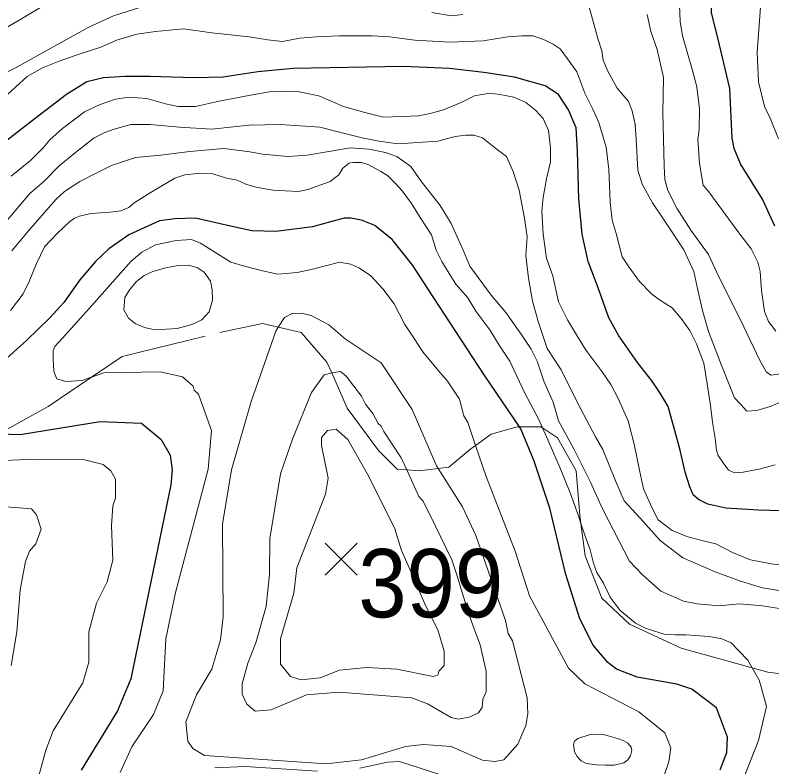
# Model space of a CAD drawing. Extents: x 474.5 to 500, y 7345.7 to 7373.4.
# Drawn here: x 484.682 to 485.568, y 7367.259 to 7368.139 of the extents above; entities that cross this region are included whole.
import ezdxf
from ezdxf.enums import TextEntityAlignment as Align

# ---------------------------------------------------------------- set-up
doc = ezdxf.new("R2010")
doc.units = 0
doc.header["$LTSCALE"] = 0.032
doc.linetypes.add('SHORT_DASHED', pattern=[2.7, 1.5, -1.2])
for name, color, linetype, lineweight in [('1', 7, 'Continuous', 25), ('16', 7, 'SHORT_DASHED', 13), ('2', 7, 'Continuous', 13), ('21', 7, 'Continuous', 25)]:
    doc.layers.add(name, color=color, linetype=linetype, lineweight=lineweight)
doc.layers.add('61', color=7, linetype='Continuous')

msp = doc.modelspace()

# ---------------------------------------------------------------- linework, layer by layer
at = {"layer": '1'}
for points in [[(485.5714, 7367.8924), (485.5571, 7367.9237), (485.5312, 7367.9653), (485.5237, 7367.983), (485.5216, 7367.9953), (485.5189, 7368.0532), (485.5134, 7368.0764), (485.5066, 7368.1044), (485.4971, 7368.1425), (485.4964, 7368.1752), (485.5039, 7368.2073), (485.508, 7368.2216), (485.5134, 7368.2359), (485.5243, 7368.2509), (485.5448, 7368.2727), (485.5666, 7368.2952), (485.5789, 7368.3109)], [(485.6463, 7367.5573), (485.5524, 7367.5597), (485.514, 7367.562), (485.4929, 7367.5667), (485.4819, 7367.5722), (485.4757, 7367.5777), (485.4718, 7367.5871), (485.4663, 7367.6043), (485.4608, 7367.6301), (485.4538, 7367.6544), (485.4467, 7367.681), (485.4373, 7367.6966), (485.4279, 7367.7107), (485.4107, 7367.7326), (485.3888, 7367.7639), (485.3771, 7367.785), (485.3646, 7367.8202), (485.3528, 7367.8508), (485.3458, 7367.8828), (485.3419, 7367.9243), (485.3403, 7367.9799), (485.3387, 7368.0073), (485.3301, 7368.0284), (485.3184, 7368.0464), (485.3027, 7368.0566), (485.2668, 7368.0667), (485.2308, 7368.0722), (485.1908, 7368.0769), (485.1369, 7368.0792), (485.05, 7368.0777), (485.0077, 7368.0769), (484.9663, 7368.073), (484.9256, 7368.0667), (484.8919, 7368.0659), (484.8403, 7368.0675), (484.8106, 7368.0675), (484.7855, 7368.0659), (484.766, 7368.0613), (484.7425, 7368.0464), (484.7057, 7368.0182), (484.6674, 7367.9885)], [(485.5073, 7367.2558), (485.5153, 7367.2764), (485.516, 7367.2941), (485.5033, 7367.3284), (485.4741, 7367.3502), (485.4567, 7367.3562), (485.4104, 7367.3644), (485.386, 7367.3736), (485.3759, 7367.3817), (485.3589, 7367.402), (485.3433, 7367.4325), (485.3268, 7367.4847), (485.3082, 7367.562), (485.2898, 7367.6173), (485.2741, 7367.655), (485.2724, 7367.6575), (485.2313, 7367.7183), (485.165, 7367.8195), (485.1478, 7367.8461), (485.1236, 7367.8766), (485.1032, 7367.893), (485.0876, 7367.8993), (485.075, 7367.9016), (485.0672, 7367.9016), (485.0531, 7367.8977), (485.0304, 7367.8915), (484.9874, 7367.886), (484.9592, 7367.8868), (484.9342, 7367.8922), (484.8935, 7367.9016), (484.8692, 7367.9008), (484.8512, 7367.8985), (484.8153, 7367.8821), (484.7918, 7367.8656), (484.7761, 7367.8508), (484.7581, 7367.8296), (484.7394, 7367.803), (484.7229, 7367.785), (484.6955, 7367.7584), (484.665, 7367.731)], [(484.6628, 7367.6491), (484.6883, 7367.6484), (484.7818, 7367.6635), (484.8303, 7367.6618), (484.8531, 7367.6427), (484.8635, 7367.6244), (484.8659, 7367.6071), (484.8643, 7367.5893), (484.8176, 7367.3624), (484.8022, 7367.3248), (484.7597, 7367.2556)]]:
    msp.add_lwpolyline(points, dxfattribs=at)
at = {"layer": '16'}
msp.add_lwpolyline([(484.6628, 7367.6491), (484.721, 7367.6813), (484.7716, 7367.7155), (484.8074, 7367.7396), (484.9219, 7367.7677), (484.9716, 7367.7785), (484.9902, 7367.7741), (485.017, 7367.7677), (485.0472, 7367.7331), (485.0528, 7367.7204), (485.071, 7367.6791), (485.1077, 7367.6295), (485.1293, 7367.6079), (485.1405, 7367.607), (485.1552, 7367.6057), (485.1774, 7367.6085), (485.1897, 7367.61), (485.2157, 7367.6316), (485.2212, 7367.6356), (485.2394, 7367.6489), (485.2697, 7367.6575), (485.2724, 7367.6575), (485.2977, 7367.6575), (485.2996, 7367.6562), (485.3172, 7367.6446), (485.3388, 7367.6057), (485.3431, 7367.5539), (485.3444, 7367.5443), (485.3496, 7367.5063), (485.369, 7367.4567), (485.4014, 7367.4264), (485.4619, 7367.3983), (485.5449, 7367.3754), (485.5634, 7367.3703), (485.6649, 7367.3573)], dxfattribs=at)
at = {"layer": '2'}
for points in [[(485.5758, 7367.9946), (485.5658, 7368.0187), (485.5594, 7368.0324), (485.5524, 7368.0612), (485.5509, 7368.0958), (485.5545, 7368.1484), (485.5579, 7368.1885), (485.5636, 7368.22), (485.5795, 7368.2577)], [(485.5725, 7367.7695), (485.564, 7367.7806), (485.5592, 7367.7922), (485.5558, 7367.8171), (485.5541, 7367.839), (485.5515, 7367.8501), (485.5438, 7367.8656), (485.5292, 7367.8844), (485.4941, 7367.9325), (485.4876, 7367.9402), (485.4833, 7367.9655), (485.4812, 7367.9942), (485.4829, 7368.0054), (485.4833, 7368.0294), (485.4803, 7368.0555), (485.4752, 7368.0744), (485.4632, 7368.1152), (485.4606, 7368.1319), (485.4593, 7368.1606)], [(484.7245, 7368.1556), (484.687, 7368.1332)], [(484.8292, 7368.1486), (484.7972, 7368.1384), (484.7679, 7368.1248), (484.7249, 7368.1009), (484.6833, 7368.0778), (484.6554, 7368.0641)], [(485.2061, 7368.1398), (485.1931, 7368.1384), (485.17, 7368.1425)], [(485.4092, 7367.9939), (485.4078, 7368.011), (485.4085, 7368.0096), (485.4044, 7368.0273), (485.4003, 7368.0382), (485.3867, 7368.0539), (485.3758, 7368.0737), (485.3703, 7368.0866), (485.369, 7368.0975), (485.3642, 7368.1118), (485.3587, 7368.1316), (485.354, 7368.1486)], [(484.687, 7368.1332), (484.6372, 7368.1044)], [(485.5782, 7367.7193), (485.5673, 7367.7179), (485.5618, 7367.7213), (485.5537, 7367.735), (485.5312, 7367.7827), (485.5059, 7367.8331), (485.4937, 7367.859), (485.4732, 7367.8876), (485.4569, 7367.9135), (485.446, 7367.934), (485.4426, 7367.9469), (485.4419, 7367.9626), (485.4405, 7368.0253), (485.4412, 7368.0662), (485.4337, 7368.0989), (485.4262, 7368.12), (485.4221, 7368.1398)], [(485.23, 7368.109), (485.1916, 7368.1074), (485.1502, 7368.1098), (485.1204, 7368.1137), (485.1001, 7368.1152), (485.061, 7368.1152), (485.0351, 7368.1137), (485.0156, 7368.1121), (484.9952, 7368.1082), (484.978, 7368.1105), (484.9561, 7368.1137), (484.9342, 7368.116), (484.9123, 7368.1184), (484.8794, 7368.1231), (484.8466, 7368.1199), (484.8246, 7368.1168), (484.802, 7368.1105), (484.7824, 7368.1019), (484.755, 7368.0926), (484.7339, 7368.0855), (484.7143, 7368.0777), (484.6963, 7368.0675), (484.6689, 7368.0425)], [(485.5719, 7367.6129), (485.5547, 7367.6082), (485.5344, 7367.6043), (485.5242, 7367.6035), (485.5171, 7367.6066), (485.5109, 7367.6152), (485.505, 7367.624), (485.5031, 7367.6301), (485.5015, 7367.6442), (485.4984, 7367.663), (485.496, 7367.6825), (485.4921, 7367.7076), (485.4882, 7367.7318), (485.4796, 7367.7545), (485.4718, 7367.7702), (485.4616, 7367.7842), (485.4514, 7367.7968), (485.4366, 7367.8062), (485.4272, 7367.8132), (485.4131, 7367.8273), (485.4006, 7367.8445), (485.3927, 7367.8562), (485.3857, 7367.8836), (485.381, 7367.8993), (485.3786, 7367.9204), (485.3771, 7367.9587), (485.374, 7367.9846), (485.3653, 7368.0135), (485.3583, 7368.0292), (485.3489, 7368.0479), (485.3395, 7368.073), (485.3286, 7368.0879), (485.32, 7368.0996), (485.3121, 7368.1051), (485.3027, 7368.1098), (485.2887, 7368.1152), (485.2754, 7368.1152), (485.2589, 7368.1137), (485.23, 7368.109)], [(485.1345, 7368.0206), (485.1134, 7368.0198), (485.0915, 7368.0253), (485.0664, 7368.0323), (485.0523, 7368.0386), (485.0375, 7368.0448), (485.0148, 7368.0495), (484.9843, 7368.0503), (484.9577, 7368.0456), (484.9209, 7368.0386), (484.8935, 7368.0323), (484.8732, 7368.0323), (484.8583, 7368.0354), (484.8364, 7368.0417), (484.8153, 7368.0433), (484.7996, 7368.0409), (484.7816, 7368.0346), (484.7636, 7368.026), (484.7378, 7368.0065), (484.7229, 7367.9932), (484.7151, 7367.9838), (484.7002, 7367.9689), (484.6775, 7367.9509)], [(485.611, 7367.4924), (485.5672, 7367.4971), (485.543, 7367.5018), (485.5218, 7367.5104), (485.5023, 7367.5206), (485.4858, 7367.5245), (485.4686, 7367.5292), (485.4514, 7367.5362), (485.435, 7367.5487), (485.4279, 7367.562), (485.4178, 7367.5847), (485.4131, 7367.6066), (485.4068, 7367.6371), (485.3998, 7367.6645), (485.388, 7367.6904), (485.3794, 7367.7068), (485.3693, 7367.7217), (485.3505, 7367.7467), (485.3403, 7367.7631), (485.3286, 7367.7827), (485.3184, 7367.8038), (485.3114, 7367.8343), (485.3043, 7367.8547), (485.3004, 7367.8828), (485.2988, 7367.9102), (485.3004, 7367.9259), (485.3043, 7367.9478), (485.309, 7367.9674), (485.309, 7367.9838), (485.3067, 7368.0041), (485.3004, 7368.0182), (485.2918, 7368.0276), (485.2801, 7368.037), (485.266, 7368.0433), (485.2495, 7368.0464), (485.2378, 7368.0479), (485.2198, 7368.0448), (485.2042, 7368.037), (485.1838, 7368.0284), (485.1697, 7368.0245), (485.1549, 7368.0213), (485.1345, 7368.0206)], [(485.5813, 7367.465), (485.5571, 7367.4689), (485.5312, 7367.4767), (485.5015, 7367.4877), (485.4639, 7367.5041), (485.4373, 7367.5245), (485.4139, 7367.5503), (485.3951, 7367.5706), (485.3849, 7367.5941), (485.37, 7367.6309), (485.3614, 7367.6457), (485.3395, 7367.6872), (485.3215, 7367.724), (485.3051, 7367.749), (485.2949, 7367.7796), (485.2879, 7367.8046), (485.2832, 7367.8312), (485.2801, 7367.8578), (485.2816, 7367.8797), (485.2785, 7367.9016), (485.2722, 7367.9345), (485.2652, 7367.9564), (485.2574, 7367.9736), (485.2448, 7367.983), (485.2292, 7367.9955), (485.219, 7367.9987), (485.2096, 7367.9987), (485.1971, 7367.9971), (485.1768, 7367.9916), (485.1306, 7367.9885), (485.1079, 7367.9916), (485.0883, 7367.9955), (485.0602, 7368.0026), (485.039, 7368.008), (484.9929, 7368.0112), (484.9561, 7368.0104), (484.9123, 7368.0057), (484.8747, 7368.008), (484.8403, 7368.0112), (484.8176, 7368.0112), (484.798, 7368.0057), (484.7871, 7368.0018), (484.7746, 7367.9955), (484.7527, 7367.9783), (484.7339, 7367.9627), (484.7159, 7367.9447), (484.6994, 7367.9306), (484.6627, 7367.8875)], [(485.5809, 7367.6873), (485.5659, 7367.6811), (485.5502, 7367.6764), (485.5387, 7367.6757), (485.5312, 7367.6839), (485.5243, 7367.6913), (485.5087, 7367.7302), (485.4937, 7367.769), (485.4869, 7367.7936), (485.4814, 7367.8174), (485.4766, 7367.8392), (485.4651, 7367.8645), (485.4419, 7367.8992), (485.4283, 7367.9197), (485.416, 7367.9415), (485.4112, 7367.9578), (485.4092, 7367.9939)], [(485.0516, 7367.9799), (485.0242, 7367.9752), (485.0015, 7367.9736), (484.9718, 7367.9767), (484.9569, 7367.9791), (484.9264, 7367.983), (484.8867, 7367.9798), (484.8528, 7367.9752), (484.8231, 7367.9728), (484.7949, 7367.9634), (484.7777, 7367.9548), (484.7581, 7367.9447), (484.7401, 7367.9329), (484.73, 7367.9235), (484.6979, 7367.8868), (484.6783, 7367.8633)], [(485.5868, 7367.4431), (485.5571, 7367.4478), (485.5297, 7367.4501), (485.5062, 7367.4478), (485.4804, 7367.4501), (485.4647, 7367.4533), (485.4561, 7367.4572), (485.4381, 7367.465), (485.4162, 7367.4846), (485.4013, 7367.5002), (485.3888, 7367.5245), (485.37, 7367.5605), (485.3552, 7367.5933), (485.3364, 7367.6309), (485.3184, 7367.6645), (485.3121, 7367.6864), (485.3012, 7367.7107), (485.2934, 7367.7342), (485.2863, 7367.7483), (485.2754, 7367.7647), (485.2566, 7367.7913), (485.2394, 7367.8116), (485.2143, 7367.8453), (485.2065, 7367.8641), (485.1924, 7367.8954), (485.1799, 7367.9165), (485.1572, 7367.9454), (485.1455, 7367.9619), (485.129, 7367.9736), (485.1157, 7367.9783), (485.0962, 7367.9822), (485.0743, 7367.9838), (485.0516, 7367.9799)], [(485.5557, 7367.3517), (485.5531, 7367.3609), (485.5449, 7367.3754), (485.5398, 7367.3844), (485.5289, 7367.3954), (485.5203, 7367.4047), (485.5093, 7367.4094), (485.4945, 7367.4118), (485.478, 7367.4133), (485.4671, 7367.4141), (485.4553, 7367.4141), (485.442, 7367.4149), (485.4209, 7367.4212), (485.4084, 7367.4274), (485.399, 7367.4353), (485.3904, 7367.4423), (485.3786, 7367.458), (485.3708, 7367.4744), (485.363, 7367.4869), (485.3591, 7367.4979), (485.3552, 7367.5135), (485.3489, 7367.5307), (485.3444, 7367.5443), (485.3419, 7367.5519), (485.3317, 7367.58), (485.32, 7367.609), (485.3074, 7367.6387), (485.2996, 7367.6562), (485.2949, 7367.6669), (485.2785, 7367.6974), (485.2613, 7367.7342), (485.2488, 7367.7529), (485.2378, 7367.7709), (485.2214, 7367.7929), (485.212, 7367.8085), (485.1979, 7367.8242), (485.1901, 7367.8367), (485.1815, 7367.8508), (485.1752, 7367.8641), (485.1697, 7367.8821), (485.1564, 7367.9024), (485.1462, 7367.9188), (485.1353, 7367.9337), (485.1275, 7367.9423), (485.1181, 7367.9517), (485.1103, 7367.9564), (485.0962, 7367.9642), (485.0876, 7367.9666), (485.0774, 7367.9666), (485.0727, 7367.9658), (485.0696, 7367.9634), (485.0657, 7367.9603), (485.061, 7367.9525), (485.0508, 7367.9447), (485.025, 7367.9353), (485.014, 7367.9329), (484.9984, 7367.9337), (484.9843, 7367.9345), (484.9749, 7367.9361), (484.9624, 7367.9384), (484.9522, 7367.9415), (484.942, 7367.9462), (484.9295, 7367.9486), (484.9138, 7367.9533), (484.8959, 7367.954), (484.881, 7367.9525), (484.8692, 7367.9486), (484.852, 7367.9384), (484.8403, 7367.9314), (484.8215, 7367.9196), (484.8153, 7367.9141), (484.8059, 7367.9102), (484.7933, 7367.9087), (484.7707, 7367.9071), (484.7574, 7367.904), (484.7519, 7367.9016), (484.7464, 7367.8977), (484.7315, 7367.8836), (484.7167, 7367.868), (484.7073, 7367.8484), (484.6987, 7367.8273), (484.6916, 7367.8132), (484.6768, 7367.7936)], [(485.4417, 7367.2492), (485.4474, 7367.2652), (485.4497, 7367.2816), (485.4428, 7367.2992), (485.4121, 7367.3238), (485.3491, 7367.3565), (485.3301, 7367.3748), (485.2844, 7367.4595), (485.2675, 7367.5118), (485.2335, 7367.5992), (485.2212, 7367.6356), (485.2122, 7367.6625), (485.2073, 7367.6702), (485.2025, 7367.6898), (485.1883, 7367.7107), (485.1783, 7367.7224), (485.1596, 7367.7451), (485.1494, 7367.7608), (485.1384, 7367.7772), (485.1259, 7367.8015), (485.1126, 7367.8187), (485.0985, 7367.8343), (485.0852, 7367.8429), (485.075, 7367.8476), (485.0617, 7367.85), (485.05, 7367.8468), (485.0289, 7367.8414), (485.0124, 7367.8382), (484.9898, 7367.8359), (484.9718, 7367.8398), (484.9506, 7367.8453), (484.9347, 7367.8502), (484.899, 7367.8723), (484.8885, 7367.8765), (484.8706, 7367.8754), (484.8465, 7367.8702), (484.8307, 7367.8618), (484.8181, 7367.8513), (484.7656, 7367.7924), (484.7372, 7367.7609), (484.7288, 7367.7515), (484.7267, 7367.7462), (484.7267, 7367.7357), (484.7277, 7367.7231), (484.7288, 7367.7189), (484.7309, 7367.7136), (484.7414, 7367.7105), (484.7603, 7367.7115), (484.7716, 7367.7155), (484.786, 7367.7205), (484.8518, 7367.7217), (484.878, 7367.7159), (484.8905, 7367.705), (484.8916, 7367.7002), (484.8968, 7367.6956), (484.9121, 7367.6531), (484.908, 7367.6079), (484.87, 7367.4635), (484.8588, 7367.4093), (484.8555, 7367.3484), (484.844, 7367.3206), (484.8188, 7367.2829), (484.8053, 7367.2529)], [(484.6507, 7367.6173), (484.7051, 7367.6197)], [(484.7051, 7367.6197), (484.7633, 7367.6188), (484.7853, 7367.6132), (484.7942, 7367.6059), (484.7997, 7367.5963), (484.7997, 7367.5739), (484.7965, 7367.5648), (484.795, 7367.5416), (484.7965, 7367.5015), (484.7901, 7367.476), (484.7776, 7367.4511), (484.7686, 7367.4173), (484.7685, 7367.3819), (484.7613, 7367.3577), (484.7269, 7367.3015), (484.718, 7367.2788), (484.7023, 7367.2205)], [(484.6465, 7367.5655), (484.7013, 7367.5614), (484.7073, 7367.5545), (484.7126, 7367.5377), (484.7065, 7367.5204), (484.6989, 7367.512), (484.6944, 7367.4999), (484.6881, 7367.4667), (484.6841, 7367.4176), (484.6775, 7367.3782)], [(485.5322, 7367.2389), (485.5523, 7367.2904), (485.5616, 7367.3299), (485.5557, 7367.3517)], [(485.0856, 7367.2578), (485.1181, 7367.2649), (485.132, 7367.2656), (485.1936, 7367.2456)], [(484.9159, 7367.2582), (484.9514, 7367.2599), (485.0363, 7367.2543)]]:
    msp.add_lwpolyline(points, dxfattribs=at)
for points in [[(484.8094, 7367.7942), (484.8105, 7367.8086), (484.816, 7367.8179), (484.8243, 7367.8273), (484.8331, 7367.8345), (484.8434, 7367.8392), (484.8588, 7367.8434), (484.8729, 7367.8461), (484.8848, 7367.8464), (484.8953, 7367.8439), (484.9036, 7367.8384), (484.911, 7367.8279), (484.913, 7367.8179), (484.9132, 7367.8058), (484.9094, 7367.792), (484.9008, 7367.7826), (484.8892, 7367.7771), (484.8718, 7367.7726), (484.853, 7367.7713), (484.8422, 7367.7715), (484.8337, 7367.7738), (484.8226, 7367.7782), (484.8149, 7367.7845)], [(485.0684, 7367.7605), (485.0493, 7367.7767), (485.0288, 7367.7877), (485.0175, 7367.7904), (485.0066, 7367.79), (484.9975, 7367.7854), (484.9902, 7367.7741), (484.9872, 7367.7695), (484.9585, 7367.6869), (484.9354, 7367.6071), (484.925, 7367.5436), (484.9258, 7367.4351), (484.9226, 7367.408), (484.9123, 7367.3736), (484.8946, 7367.3436), (484.8819, 7367.312), (484.8842, 7367.2896), (484.8902, 7367.281), (484.9038, 7367.2727), (485.0461, 7367.2628), (485.0876, 7367.2677), (485.139, 7367.2831), (485.1601, 7367.2854), (485.1924, 7367.2832), (485.2292, 7367.2672), (485.2438, 7367.2655), (485.2542, 7367.2678), (485.2706, 7367.2858), (485.28, 7367.3079), (485.2824, 7367.3216), (485.2815, 7367.3402), (485.2642, 7367.4069), (485.2593, 7367.4154), (485.2562, 7367.4308), (485.2215, 7367.53), (485.2059, 7367.5636), (485.1774, 7367.6085), (485.1754, 7367.6116), (485.1468, 7367.6775), (485.1107, 7367.7322)], [(485.1742, 7367.541), (485.1598, 7367.5703), (485.1548, 7367.5759), (485.1405, 7367.607), (485.1339, 7367.6212), (485.1136, 7367.6518), (485.1105, 7367.658), (485.1073, 7367.6614), (485.1008, 7367.6729), (485.0924, 7367.6839), (485.0875, 7367.6932), (485.0696, 7367.7167), (485.0629, 7367.722), (485.0556, 7367.7211), (485.0528, 7367.7204), (485.044, 7367.7184), (485.0293, 7367.6974), (485.0067, 7367.6428), (484.9928, 7367.6024), (484.9803, 7367.5267), (484.9799, 7367.4847), (484.9761, 7367.447), (484.9641, 7367.4045), (484.9545, 7367.3806), (484.9481, 7367.3566), (484.9481, 7367.3445), (484.9536, 7367.3326), (484.9633, 7367.3245), (484.9818, 7367.3261), (485.0233, 7367.3437), (485.061, 7367.3469), (485.1465, 7367.3403), (485.1649, 7367.3332), (485.1925, 7367.3171), (485.2008, 7367.3151), (485.2137, 7367.3175), (485.2246, 7367.3227), (485.2288, 7367.3288), (485.2296, 7367.3385), (485.2336, 7367.3471), (485.2336, 7367.3713), (485.2266, 7367.4024), (485.221, 7367.4165), (485.2133, 7367.4382), (485.1986, 7367.4863), (485.1935, 7367.5016)], [(485.1768, 7367.4197), (485.1842, 7367.3948), (485.1842, 7367.3782), (485.178, 7367.3714), (485.1769, 7367.3669), (485.1715, 7367.3653), (485.1289, 7367.3739), (485.0938, 7367.3755), (485.0619, 7367.3724), (485.0393, 7367.3636), (485.0167, 7367.3612), (485.0047, 7367.3653), (484.9929, 7367.3797), (484.9928, 7367.4092), (485.0086, 7367.4626), (485.012, 7367.4923), (485.0455, 7367.5784), (485.0486, 7367.5973), (485.0407, 7367.6354), (485.0407, 7367.6448), (485.048, 7367.6531), (485.058, 7367.6546), (485.0717, 7367.6427), (485.0963, 7367.5992), (485.1265, 7367.538), (485.1345, 7367.5126), (485.1469, 7367.4845), (485.1626, 7367.4482)], [(485.3628, 7367.2619), (485.3507, 7367.2635), (485.3447, 7367.2666), (485.34, 7367.2717), (485.337, 7367.2769), (485.3357, 7367.2856), (485.337, 7367.2896), (485.3409, 7367.2926), (485.3554, 7367.2973), (485.3692, 7367.2978), (485.3762, 7367.2959), (485.3872, 7367.2926), (485.3938, 7367.2903), (485.3993, 7367.2871), (485.4033, 7367.2824), (485.4042, 7367.2784), (485.4023, 7367.2723), (485.3993, 7367.2678), (485.3946, 7367.2643), (485.3832, 7367.2614), (485.3727, 7367.2613)]]:
    msp.add_lwpolyline(points, close=True, dxfattribs=at)
at = {"layer": '21'}
for p, q in [((485.045, 7367.5212), (485.0825, 7367.4837)), ((485.0825, 7367.5212), (485.045, 7367.4837))]:
    msp.add_line(p, q, dxfattribs=at)

# ---------------------------------------------------------------- texts
at = {"layer": '61', "width": 0.95}
msp.add_text('399', height=0.08, dxfattribs=at).set_placement((485.1687, 7367.4344), align=Align.CENTER)

doc.saveas('drawing.dxf')
